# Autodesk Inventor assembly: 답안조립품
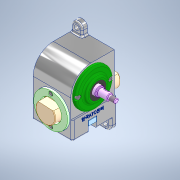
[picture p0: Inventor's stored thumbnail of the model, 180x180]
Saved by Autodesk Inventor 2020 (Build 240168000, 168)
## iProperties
Created: 2023-09
Part Number: 답안조립품
Document SubType Name: Assembly
Designer: oem
Author: oem
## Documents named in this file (11)
- C:\Users\oem\Desktop\730906V1009\답안조립품.iam
- C:\Users\oem\Desktop\730906V1009\본체.ipt
- C:\Users\oem\Desktop\730906V1009\가이드 부시.ipt
- C:\Users\oem\Desktop\730906V1009\부시 커버.ipt
- C:\Users\oem\Desktop\730906V1009\볼트 M4.ipt
- C:\Users\oem\Desktop\730906V1009\래크.ipt
- C:\Users\oem\Desktop\730906V1009\스톱퍼.ipt
- C:\Users\oem\Desktop\730906V1009\베어링 6003.ipt
- C:\Users\oem\Desktop\730906V1009\피니언.ipt
- C:\Users\oem\Desktop\730906V1009\앞커버.ipt
- C:\Users\oem\Desktop\730906V1009\오일 실 17 30 5.ipt
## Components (3 placed, 2 different names)
1. 가이드 부시:1
2. 가이드 부시:2
3. 피니언:1
